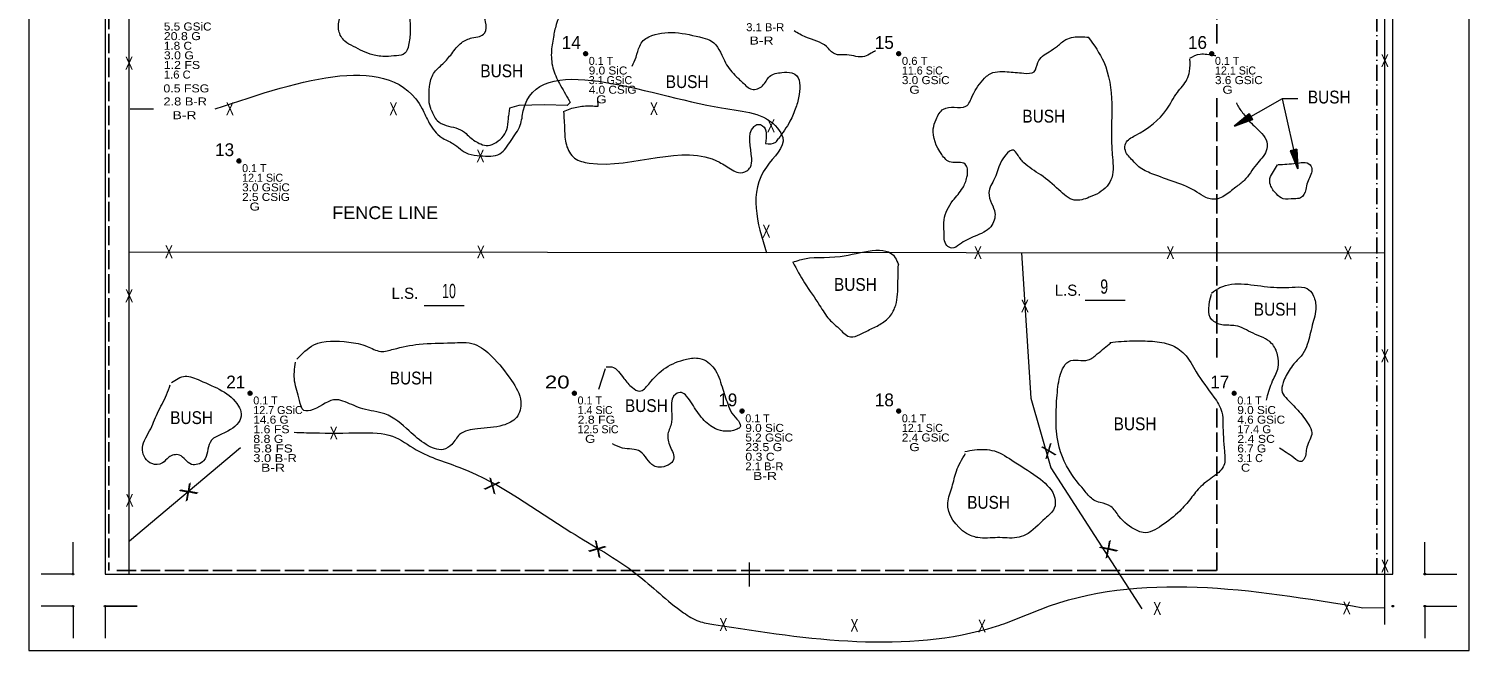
# Model space of a CAD drawing. Extents: x -496 to 480, y -452 to 700.
# Drawn here: x -450 to 450, y -452 to -62 of the extents above; entities that cross this region are included whole.
import ezdxf
from ezdxf.enums import TextEntityAlignment as Align

# ---------------------------------------------------------------- set-up
doc = ezdxf.new("R2010")
doc.units = 0
doc.header["$LTSCALE"] = 2
doc.header["$PDMODE"] = 32
doc.header["$PDSIZE"] = 1
doc.linetypes.add('DOT_DASHED', pattern=[7.7, 5, -1.2, 0.3, -1.2])
doc.linetypes.add('LONG_DASHED', pattern=[7.5, 6, -1.5])
doc.layers.add('3', color=7, linetype='Continuous', lineweight=13)

msp = doc.modelspace()

# ---------------------------------------------------------------- linework, layer by layer
at = {"layer": '3'}
for p, q in [((-402.391, 402.339), (-402.391, -402.333)), ((397.281, -433.821), (397.281, 402.339)), ((-387.448, 109.099), (-387.448, -402.333)), ((-94.215, -110.175), (-94.393, -105.912)), ((333.049, -105.528), (342.996, -149.245)), ((-386.748, -111.843), (-372.186, -111.843)), ((-387.448, -201.078), (397.281, -201.694)), ((210.113, -231.312), (235.113, -231.312)), ((-202.998, -234.618), (-177.998, -234.618)), ((-93.889, -286.957), (-89.744, -273.899)), ((-317.842, -323.532), (-387.085, -381.774)), ((-422.391, -402.333), (-422.391, -382.333)), ((422.281, -402.333), (422.281, -382.333)), ((-0.017, -395.027), (-0.017, -410.027)), ((-422.391, -402.333), (-442.391, -402.333)), ((-402.391, -402.333), (402.281, -402.333)), ((422.281, -402.333), (442.281, -402.333)), ((-422.391, -422.333), (-442.391, -422.333)), ((-422.391, -422.333), (-422.391, -442.333)), ((-402.391, -422.333), (-402.391, -442.333)), ((422.281, -422.333), (422.281, -442.333)), ((422.281, -422.333), (442.281, -422.333)), ((383.619, -423.303), (396.939, -423.155)), ((-450.017, -450.027), (449.983, -450.027))]:
    msp.add_line(p, q, dxfattribs=at)
at = {"layer": '3', "linetype": 'LONG_DASHED', "lineweight": 25}
for p, q in [((-400, 400), (-400, -400)), ((292.281, 15.922), (292.281, -71.709)), ((292.281, -105.114), (292.281, -270.064)), ((292.281, -298.887), (292.281, -400)), ((-395, -400), (292.281, -400))]:
    msp.add_line(p, q, dxfattribs=at)
at = {"layer": '3', "linetype": 'DOT_DASHED', "lineweight": 25}
msp.add_line((392.281, -402.333), (392.281, 402.339), dxfattribs=at)
at = {"layer": '3'}
for points in [[(449.983, -450.027), (449.983, 399.973), (449.983, 699.973), (-450.017, 699.973), (-450.017, 49.973), (-450.017, -450.027)], [(402.281, -402.333), (402.281, 402.339), (-402.391, 402.339)], [(-198.602, -112.393), (-199.82, -108.116), (-199.95, -106.612)], [(-111.718, -107.854), (-113.576, -109.839), (-127.591, -109.408), (-143.761, -109.839), (-149.583, -111.347), (-150.19, -116.354)], [(342.996, -105.528), (333.049, -105.528), (303.207, -122.75)], [(170.245, -201.672), (176.021, -292.42), (188.67, -335.937), (245.355, -423.908)], [(-402.391, -422.333), (-382.391, -422.333), (-402.391, -422.333)]]:
    msp.add_lwpolyline(points, dxfattribs=at)
at = {"layer": '3', "lineweight": 25}
for points in [[(303.207, -122.75), (314.6, -118.484), (312.601, -115.019)], [(342.996, -149.245), (342.284, -137.1), (338.383, -137.987)]]:
    msp.add_lwpolyline(points, close=True, dxfattribs=at)
for points in [[(314.456, -118.43), (303.705, -122.463), (312.542, -115.243), (314.331, -118.302), (304.343, -122.095), (312.459, -115.488), (314.108, -118.257), (305.017, -121.706), (312.4, -115.774), (313.888, -118.135), (305.793, -121.282), (312.29, -116.062), (313.59, -118.056), (306.724, -120.772), (312.251, -116.384), (313.274, -117.938), (307.725, -120.218), (312.171, -116.805), (312.931, -117.864), (308.845, -119.647), (312.002, -117.202), (312.521, -117.801), (310.127, -118.883), (311.848, -117.713)], [(342.19, -137.222), (342.869, -148.685), (338.58, -138.11), (342.03, -137.303), (342.706, -147.967), (338.79, -138.261), (341.922, -137.504), (342.533, -147.208), (339.045, -138.403), (341.74, -137.678), (342.357, -146.341), (339.288, -138.592), (341.576, -137.939), (342.145, -145.301), (339.584, -138.725), (341.371, -138.206), (341.911, -144.181), (339.963, -138.926), (341.198, -138.512), (341.696, -142.942), (340.292, -139.204), (341.017, -138.885), (341.345, -141.492), (340.735, -139.503)]]:
    msp.add_lwpolyline(points, dxfattribs=at)
at = {"layer": '3', "lineweight": 35}
for centre in [(-102.135, -77.412), (93.501, -77.412), (289.137, -77.412), (-318.732, -144.354), (-311.745, -289.395), (-109.122, -289.395), (303.111, -289.395), (-4.317, -300.552), (93.501, -300.552)]:
    msp.add_circle(centre, 1, dxfattribs=at)
at = {"layer": '3'}
for points in [[(-199.95, -106.612), (-199.61, -97.793), (-197.09, -89.738), (-191.294, -83.697), (-185.749, -77.403), (-179.701, -70.607), (-173.149, -67.586), (-168.36, -66.579), (-165.336, -64.566), (-164.58, -57.517), (-168.108, -48.959), (-168.612, -41.155), (-165.084, -35.869), (-147.191, -17.745), (-144.671, -12.962), (-138.623, -11.452), (-133.834, -11.2), (-127.03, -13.969), (-118.461, -28.318), (-115.689, -38.638), (-116.697, -48.959), (-120.477, -59.279), (-122.242, -67.083), (-123.502, -76.9), (-122.242, -87.472), (-117.705, -97.29), (-111.718, -107.854)], [(-224.812, -25.549), (-221.787, -25.549), (-216.747, -30.835), (-214.227, -39.645), (-212.211, -53.238), (-211.707, -63.559), (-212.715, -72.117), (-214.983, -77.152), (-220.275, -78.662), (-226.828, -79.166), (-235.144, -78.159), (-247.241, -72.872), (-252.533, -69.6), (-256.313, -63.055), (-255.557, -54.748), (-250.517, -47.197), (-242.453, -39.897), (-236.404, -34.107), (-225.568, -26.052)], [(-72.964, -85.265), (-70.596, -79.476), (-68.319, -72.654), (-66.042, -69.243), (-62.627, -66.969), (-28.763, -67.537), (-23.356, -69.527), (-15.388, -81.75), (-8.842, -90.846), (-4.004, -95.394), (1.687, -99.657), (8.517, -97.383), (12.786, -91.698), (20.469, -89.14), (26.73, -89.424), (28.722, -90.277), (31.283, -102.784), (29.291, -111.027), (25.592, -119.555), (18.477, -130.356)], [(79.021, -75.667), (76.415, -77.019), (72.118, -79.165), (61.107, -78.092), (53.587, -77.556), (48.484, -72.995), (35.593, -67.094), (28.107, -63.151)], [(212.003, -67.12), (221.632, -82.566), (226.593, -108.505), (226.885, -140.273), (226.593, -154.845), (223.675, -160.091), (212.587, -167.086), (203.25, -168.835), (193.621, -162.423), (182.241, -153.097), (171.737, -145.519), (167.652, -140.273), (165.318, -137.65), (160.357, -140.564), (153.354, -155.428), (149.853, -164.172), (151.604, -170.875), (153.646, -176.704), (151.02, -185.447), (141.391, -191.276), (131.471, -196.522), (126.802, -198.854), (123.592, -197.105), (121.842, -188.653), (121.842, -181.076), (127.386, -169.126), (133.513, -161.257), (136.139, -154.554), (136.431, -149.308), (134.972, -146.393), (126.218, -145.228), (120.383, -140.273), (115.13, -124.243), (116.881, -118.414), (121.55, -112.003), (128.261, -110.837), (135.556, -110.254), (139.641, -103.551), (147.227, -92.767), (149.853, -90.435), (161.233, -88.687), (171.737, -89.561), (178.156, -88.687), (180.491, -82.858), (187.493, -76.154), (192.746, -72.657), (197.998, -68.577), (202.666, -67.12), (212.295, -67.12)], [(-333.576, -111.843), (-204.225, -111.843), (-199.758, -120.767), (-192.099, -129.692), (-185.079, -133.516), (-175.506, -139.891), (-167.848, -141.166), (-155.722, -139.891), (-148.702, -131.604), (-142.959, -122.042), (-141.044, -113.118), (-17.235, -111.205), (17.866, -123.955), (21.057, -129.692), (10.846, -148.178), (10.846, -201.724)], [(304.514, -108.169), (304.554, -108.267), (308.366, -114.279), (312.981, -119.89), (320.404, -127.305), (323.614, -132.515), (323.213, -138.126), (316.993, -146.543), (309.369, -156.563), (304.153, -160.771), (296.93, -166.182), (292.918, -167.986), (285.494, -167.184), (279.877, -163.777), (266.234, -157.565), (251.789, -152.355), (243.563, -147.946), (239.751, -144.138), (235.136, -137.926), (235.337, -133.317), (241.356, -128.507), (261.018, -112.075), (267.638, -101.654), (273.657, -93.438), (275.262, -88.428), (275.463, -80.813)], [(275.463, -80.212), (281.883, -77.607), (290.51, -78.408), (291.7, -78.453)], [(-198.602, -112.393), (-194.822, -119.189), (-189.277, -122.21), (-183.229, -123.72), (-177.685, -126.489), (-174.409, -129.51), (-167.604, -133.789), (-163.068, -134.796), (-158.028, -132.782), (-153.491, -128.755), (-150.971, -123.217), (-150.19, -116.354)], [(-115.843, -113.586), (-111.747, -111.854), (-103.358, -110.121), (-94.215, -110.175)], [(-115.843, -113.586), (-115.274, -124.671), (-114.136, -134.336), (-109.013, -142.579), (-99.907, -145.706), (-18.518, -145.137), (-10.55, -149.969), (-6.566, -151.675), (-1.443, -150.538), (0.833, -148.264), (1.687, -142.863), (3.11, -122.966), (5.671, -121.544), (8.517, -122.397), (10.224, -133.483)], [(10.224, -133.483), (16.702, -132.66), (18.477, -130.356)], [(330.486, -146.573), (341.687, -145.827), (346.168, -145.33), (350.648, -146.822), (351.644, -149.805), (348.906, -157.761), (347.91, -162.237), (344.674, -167.458), (340.442, -167.955), (333.722, -167.955), (329.49, -164.972), (325.756, -159.253), (325.507, -155.275), (327.747, -151.048), (330.237, -146.822)], [(27.386, -207.659), (31.696, -206.129), (57.038, -203.952), (91.373, -204.769), (93.325, -209.138)], [(27.386, -207.659), (34.72, -220.558), (44.132, -234.546), (50.101, -243.259), (56.988, -249.679), (63.416, -254.265), (69.155, -252.66), (74.435, -250.138), (81.781, -246.469), (87.979, -241.425), (91.652, -234.316), (93.03, -220.787), (93.325, -209.138)], [(288.871, -226.897), (294.206, -223.448), (325.907, -223.135), (341.286, -223.135), (348.819, -224.075), (352.271, -227.837), (354.155, -235.361), (351.958, -246.961), (348.819, -258.874), (345.994, -264.83), (341.286, -270.16), (338.148, -274.235), (333.753, -282.7), (333.126, -288.97), (336.264, -293.045), (342.855, -299.942), (349.76, -309.034), (351.644, -314.05), (348.505, -323.142), (346.936, -330.352), (345.366, -331.92), (340.345, -329.725), (331.428, -323.705)], [(323.383, -293.625), (323.71, -292.105), (327.162, -281.759), (330.615, -273.295), (330.301, -265.457), (326.535, -258.247), (314.922, -251.977), (303.936, -247.274), (295.462, -246.647), (289.185, -243.512), (288.871, -227.524)], [(-282.584, -268.13), (-271.92, -259.253), (-250.147, -257.478), (-238.595, -260.141), (-230.152, -263.248), (-222.155, -261.916), (-206.159, -258.81), (-185.719, -257.922), (-171.501, -258.81), (-160.837, -266.354), (-148.395, -281.444), (-142.619, -294.759), (-145.285, -304.523), (-153.727, -309.405), (-169.723, -311.624), (-180.832, -315.174), (-185.719, -321.388), (-191.051, -324.495), (-201.715, -321.388), (-212.379, -312.955), (-227.486, -302.304), (-241.261, -299.197), (-252.369, -294.759), (-257.701, -293.427), (-272.364, -299.641), (-278.14, -300.085), (-280.806, -293.871), (-283.917, -281.888), (-283.472, -269.905)], [(225.47, -257.62), (239.594, -256.679), (252.149, -256.993), (263.448, -259.187), (271.922, -264.83), (279.455, -276.116), (290.44, -291.791), (295.462, -301.196), (296.09, -308.407), (297.031, -325.65), (296.717, -334.428), (290.754, -341.011), (282.28, -347.595), (276.002, -355.119), (269.097, -362.956), (257.798, -372.048), (246.185, -376.437), (242.419, -375.183), (231.12, -366.091), (226.098, -360.135), (219.507, -357.627), (215.427, -356.059), (210.091, -350.73), (201.616, -340.071), (192.514, -316.872), (191.887, -301.51), (192.828, -287.089), (195.967, -274.235), (199.733, -269.533), (211.974, -268.592), (217.624, -264.83), (226.098, -257.933)], [(-89.299, -273.012), (-85.745, -273.012), (-78.191, -280.113), (-72.859, -285.882), (-68.416, -288.102), (-62.639, -283.663), (-51.975, -273.456), (-39.09, -268.13), (-30.648, -267.686), (-21.761, -273.899), (-16.873, -285.439), (-13.319, -296.09), (-10.653, -301.86), (-5.765, -310.736), (-7.987, -312.068), (-20.872, -311.624), (-28.87, -305.41), (-35.535, -296.09), (-39.09, -291.208), (-42.2, -288.989), (-45.755, -289.877), (-48.421, -307.629), (-50.642, -314.731), (-49.309, -322.719), (-47.088, -330.708), (-55.974, -335.59), (-59.529, -334.702), (-67.971, -325.826), (-79.08, -323.607), (-85.241, -321.055)], [(-360.786, -282.776), (-352.344, -278.781), (-343.013, -281.444), (-319.019, -297.422), (-317.242, -302.304), (-323.906, -312.068), (-336.792, -320.056), (-340.791, -331.596), (-348.345, -333.815), (-355.898, -328.045), (-362.563, -329.377), (-366.562, -332.927), (-373.227, -333.371), (-379.004, -324.938), (-374.56, -312.955), (-369.673, -301.86), (-363.896, -290.321), (-361.675, -284.107)], [(-284.126, -313.787), (-272.105, -314.142), (-242.681, -314.142), (-222.715, -316.241), (-208.004, -324.638), (-179.631, -336.184), (-111.326, -376.07), (-70.344, -402.31), (-40.92, -426.452), (-31.463, -431.7), (-22.005, -433.799), (154.536, -434.849), (160.841, -432.749), (181.858, -424.352), (383.619, -423.303)], [(134.899, -325.78), (140.917, -324.779), (153.288, -325.446), (165.658, -332.125), (182.04, -343.146), (191.067, -354.834), (190.733, -361.179), (185.049, -367.524), (172.679, -377.876), (167.33, -379.546), (155.294, -379.546), (142.923, -379.546), (135.902, -376.874), (124.201, -357.839), (126.875, -347.821), (129.55, -338.136), (135.234, -327.116)]]:
    msp.add_spline(points, degree=3, dxfattribs=at)
at = {"layer": '3', "lineweight": 35}
for points in [[(-102.146, -76.525), (-101.416, -76.929), (-101.264, -77.778), (-101.949, -78.306), (-102.758, -78.075), (-103.045, -77.317), (-102.798, -76.755), (-102.225, -76.587), (-101.551, -77.081), (-101.567, -77.823), (-102.084, -78.081), (-102.607, -77.912), (-102.831, -77.266), (-102.247, -76.8), (-101.809, -77.334), (-101.848, -77.817), (-102.477, -77.682), (-102.331, -77.047), (-102.039, -77.598)], [(93.49, -76.525), (94.22, -76.929), (94.372, -77.778), (93.687, -78.306), (92.878, -78.075), (92.591, -77.317), (92.838, -76.755), (93.411, -76.587), (94.085, -77.081), (94.069, -77.823), (93.552, -78.081), (93.029, -77.912), (92.805, -77.266), (93.389, -76.8), (93.827, -77.334), (93.788, -77.817), (93.159, -77.682), (93.305, -77.047), (93.597, -77.598)], [(289.126, -76.525), (289.856, -76.929), (290.008, -77.778), (289.323, -78.306), (288.514, -78.075), (288.227, -77.317), (288.474, -76.755), (289.047, -76.587), (289.721, -77.081), (289.705, -77.823), (289.188, -78.081), (288.665, -77.912), (288.441, -77.266), (289.025, -76.8), (289.463, -77.334), (289.424, -77.817), (288.795, -77.682), (288.941, -77.047), (289.233, -77.598)], [(-318.743, -143.467), (-318.013, -143.871), (-317.861, -144.72), (-318.546, -145.248), (-319.355, -145.017), (-319.642, -144.259), (-319.395, -143.697), (-318.822, -143.529), (-318.148, -144.023), (-318.164, -144.765), (-318.681, -145.023), (-319.204, -144.854), (-319.428, -144.208), (-318.844, -143.742), (-318.406, -144.276), (-318.445, -144.759), (-319.074, -144.624), (-318.928, -143.989), (-318.636, -144.54)], [(-311.756, -288.508), (-311.026, -288.912), (-310.874, -289.761), (-311.559, -290.289), (-312.368, -290.058), (-312.655, -289.3), (-312.408, -288.738), (-311.835, -288.57), (-311.161, -289.064), (-311.177, -289.806), (-311.694, -290.064), (-312.217, -289.895), (-312.441, -289.249), (-311.857, -288.783), (-311.419, -289.317), (-311.458, -289.8), (-312.087, -289.665), (-311.941, -289.03), (-311.649, -289.581)], [(-109.133, -288.508), (-108.403, -288.912), (-108.251, -289.761), (-108.936, -290.289), (-109.745, -290.058), (-110.032, -289.3), (-109.785, -288.738), (-109.212, -288.57), (-108.538, -289.064), (-108.554, -289.806), (-109.071, -290.064), (-109.594, -289.895), (-109.818, -289.249), (-109.234, -288.783), (-108.796, -289.317), (-108.835, -289.8), (-109.464, -289.665), (-109.318, -289.03), (-109.026, -289.581)], [(303.1, -288.508), (303.83, -288.912), (303.982, -289.761), (303.297, -290.289), (302.488, -290.058), (302.201, -289.3), (302.448, -288.738), (303.021, -288.57), (303.695, -289.064), (303.679, -289.806), (303.162, -290.064), (302.639, -289.895), (302.415, -289.249), (302.999, -288.783), (303.437, -289.317), (303.398, -289.8), (302.769, -289.665), (302.915, -289.03), (303.207, -289.581)], [(-4.328, -299.665), (-3.598, -300.069), (-3.446, -300.918), (-4.131, -301.446), (-4.94, -301.215), (-5.227, -300.457), (-4.98, -299.895), (-4.407, -299.727), (-3.733, -300.221), (-3.749, -300.963), (-4.266, -301.221), (-4.789, -301.052), (-5.013, -300.406), (-4.429, -299.94), (-3.991, -300.474), (-4.03, -300.957), (-4.659, -300.822), (-4.513, -300.187), (-4.221, -300.738)], [(93.49, -299.665), (94.22, -300.069), (94.372, -300.918), (93.687, -301.446), (92.878, -301.215), (92.591, -300.457), (92.838, -299.895), (93.411, -299.727), (94.085, -300.221), (94.069, -300.963), (93.552, -301.221), (93.029, -301.052), (92.805, -300.406), (93.389, -299.94), (93.827, -300.474), (93.788, -300.957), (93.159, -300.822), (93.305, -300.187), (93.597, -300.738)]]:
    msp.add_spline(points, degree=3, dxfattribs=at)
at = {"layer": '3'}
for p in [(-422.391, -402.333), (422.281, -402.333), (-422.391, -422.333), (-402.391, -422.333), (402.281, -422.333), (422.281, -422.333)]:
    msp.add_point(p, dxfattribs=at)

# ---------------------------------------------------------------- texts
for s, width, p in [('5.5 GSiC   ', 1.1, (-365.641, -62.941)), ('3.1 B-R    ', 1.05, (-1.765, -63.367)), ('20.8 G     ', 1.15, (-365.641, -68.941)), ('1.8 C      ', 1.1, (-365.641, -74.941)), ('  B-R      ', 1.3, (-4.476, -71.688)), ('3.0 G      ', 1.15, (-365.641, -80.941)), ('0.6 T      ', 1.05, (95.501, -84.412)), ('1.6 C      ', 1.05, (-365.641, -92.941)), ('1.2 FS     ', 1.15, (-365.641, -86.941)), ('9.0 SiC    ', 1.1, (-100.135, -90.412)), ('0.5 FSG    ', 1.15, (-365.895, -101.575)), ('4.0 CSiG   ', 1.1, (-100.135, -102.412)), ('3.0 GSiC   ', 1.1, (95.501, -96.412)), ('  G        ', 1.25, (95.501, -102.412)), ('3.6 GSiC   ', 1.1, (291.137, -96.412)), ('  G        ', 1.25, (291.137, -102.412)), ('2.8 B-R    ', 1.2, (-365.895, -109.728)), ('  G        ', 1.25, (-100.135, -108.412)), ('  B-R      ', 1.3, (-365.033, -118.312)), ('3.0 GSiC   ', 1.1, (-316.732, -163.354)), ('2.5 CSiG   ', 1.1, (-316.732, -169.354)), ('  G        ', 1.25, (-316.732, -175.354)), ('14.6 G     ', 1.1, (-309.745, -308.395)), ('2.8 FG     ', 1.15, (-107.122, -308.395)), ('4.6 GSiC   ', 1.1, (305.111, -308.395)), ('9.0 SiC    ', 1.1, (305.111, -302.395)), ('1.6 FS     ', 1.15, (-309.745, -314.395)), ('5.2 GSiC   ', 1.1, (-2.317, -319.552)), ('9.0 SiC    ', 1.1, (-2.317, -313.552)), ('2.4 GSiC   ', 1.1, (95.501, -319.552)), ('17.4 G     ', 1.05, (305.111, -314.395)), ('8.8 G      ', 1.15, (-309.745, -320.395)), ('5.8 FS     ', 1.25, (-309.745, -326.395)), ('  G        ', 1.25, (-107.122, -320.395)), ('23.5 G     ', 1.15, (-2.317, -325.552)), ('  G        ', 1.25, (95.501, -325.552)), ('6.7 G      ', 1.1, (305.111, -326.395)), ('2.4 SC     ', 1.15, (305.111, -320.395)), ('3.0 B-R    ', 1.2, (-309.745, -332.395)), ('0.3 C      ', 1.15, (-2.317, -331.552)), ('2.1 B-R    ', 1.05, (-2.317, -337.552)), ('  B-R      ', 1.3, (-309.745, -338.395)), ('  B-R      ', 1.3, (-2.317, -343.552)), (' C         ', 1.2, (305.111, -338.395))]:
    msp.add_text(s, height=5, dxfattribs=dict(at, width=width)).set_placement(p)
for s, p in [(' 14', (-105.136, -74.412)), (' 15', (90.5, -74.412)), (' 16', (286.136, -74.412)), (' 13', (-321.733, -141.354)), (' 21', (-314.746, -286.395)), (' 17', (300.11, -286.395)), (' 19', (-7.318, -297.552)), (' 18', (90.5, -297.552))]:
    msp.add_text(s, height=8, dxfattribs=at).set_placement(p, align=Align.RIGHT)
for s, height, width, p in [('X', 8, 0.7, (-387.374, -87.369)), ('X', 8, 0.7, (397.279, -85.799)), ('BUSH', 8, 0.9, (-154.512, -92.11)), ('BUSH', 8, 0.9, (-38.664, -98.861)), ('X', 8, 0.7, (-324.357, -115.862)), ('X', 8, 0.7, (-222.207, -115.862)), ('X', 8, 0.7, (-59.424, -115.779)), ('BUSH', 8, 0.9, (362.552, -108.481)), ('BUSH', 8, 0.9, (184.167, -120.404)), ('X', 8, 0.7, (13.751, -126.474)), ('X', 8, 0.7, (-167.834, -145.242)), ('FENCE LINE', 8, 1.05, (-227.298, -180.687)), ('X', 8, 0.7, (10.824, -192.172)), ('X', 8, 0.7, (-362.478, -205.079)), ('X', 8, 0.7, (-167.607, -205.217)), ('X', 8, 0.7, (143.033, -205.643)), ('X', 8, 0.7, (263.259, -205.591)), ('X', 8, 0.7, (374.239, -205.779)), ('X', 8, 0.7, (-387.312, -232.55)), ('10', 8.89, 0.65, (-187.46, -230.008)), ('BUSH', 8, 0.9, (66.448, -225.467)), ('9', 8.89, 0.75, (221.931, -227.236)), ('X', 8, 0.7, (172.366, -238.939)), ('BUSH', 8, 0.9, (328.731, -240.956)), ('X', 8, 0.7, (397.311, -270.052)), ('BUSH', 8, 0.9, (-211.11, -283.908)), ('BUSH', 8, 0.9, (-64.153, -301.133)), ('BUSH', 8, 0.9, (-348.293, -308.634)), ('BUSH', 8, 0.9, (241.197, -312.493)), ('X', 8, 0.7, (-259.513, -318.201)), ('X', 8, 0.7, (-387.069, -360.249)), ('BUSH', 8, 0.9, (149.683, -361.508)), ('X', 8, 0.7, (397.351, -401.308)), ('X', 8, 0.7, (255.078, -427.812)), ('X', 8, 0.7, (373.457, -427.461)), ('X', 8, 0.7, (-16.004, -437.833)), ('X', 8, 0.7, (65.859, -438.334)), ('X', 8, 0.7, (145.559, -438.669))]:
    msp.add_text(s, height=height, dxfattribs=dict(at, width=width)).set_placement(p, align=Align.CENTER)
for s, p in [('0.1 T      ', (-100.135, -84.412)), ('0.1 T      ', (291.137, -84.412)), ('11.6 SiC   ', (95.501, -90.412)), ('12.1 SiC   ', (291.137, -90.412)), ('3.1 GSiC   ', (-100.135, -96.412)), ('0.1 T      ', (-316.732, -151.354)), ('12.1 SiC   ', (-316.732, -157.354)), ('0.1 T      ', (-309.745, -296.395)), ('0.1 T      ', (-107.122, -296.395)), ('0.1 T      ', (305.111, -296.395)), ('12.7 GSiC  ', (-309.745, -302.395)), ('1.4 SiC    ', (-107.122, -302.395)), ('0.1 T      ', (-2.317, -307.552)), ('0.1 T      ', (95.501, -307.552)), ('12.5 SiC   ', (-107.122, -314.395)), ('12.1 SiC   ', (95.501, -313.552)), ('3.1 C      ', (305.111, -332.395))]:
    msp.add_text(s, height=5, dxfattribs=at).set_placement(p)
for p in [(-215.009, -230.48), (199.339, -228.576)]:
    msp.add_text('L.S.', height=7, dxfattribs=at).set_placement(p, align=Align.CENTER)
at = {"layer": '3', "width": 1.3}
msp.add_text(' 20', height=8, dxfattribs=at).set_placement((-112.123, -286.395), align=Align.RIGHT)
at = {"layer": '3'}
for rotation, width, p in [(21.425, 1.15, (188.657, -329.157)), (335.25, 1.25, (-162.168, -350.813)), (35.028, 1.5, (-347.958, -354.281)), (329.245, 1.4, (-96.778, -390.095)), (33.481, 1.45, (226.751, -390.077))]:
    msp.add_text('X', height=8, rotation=rotation, dxfattribs=dict(at, width=width)).set_placement(p, align=Align.CENTER)

doc.saveas('drawing.dxf')
